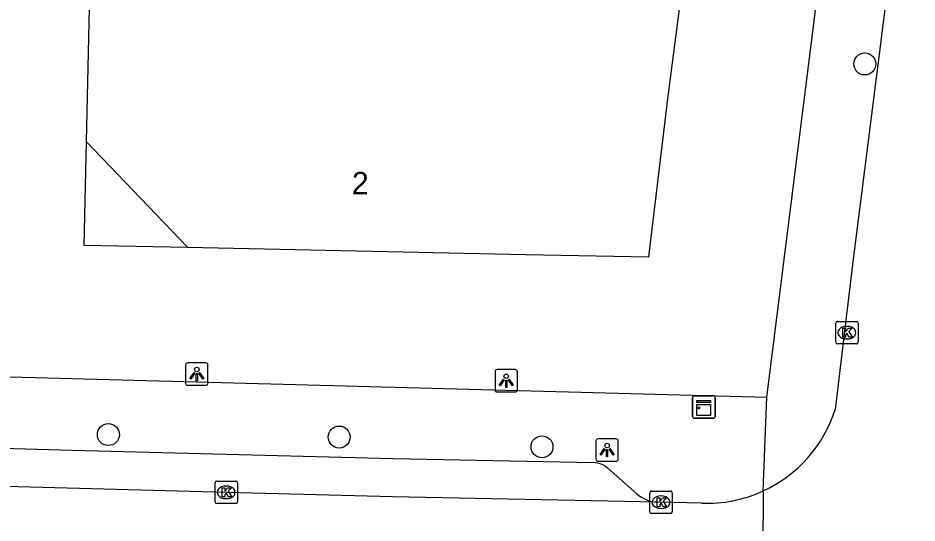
# Model space of a CAD drawing. Extents: x 160026 to 161302, y 384757 to 385701.
# Drawn here: x 160681.36 to 160721.38, y 384901.34 to 384923.84 of the extents above; entities that cross this region are included whole.
import ezdxf

# ---------------------------------------------------------------- set-up
doc = ezdxf.new("R2010")
doc.units = 0
for name, color, linetype in [('IMGEO_Boom', 7, 'Continuous'), ('IMGEO_Kast', 7, 'Continuous'), ('IMGEO_Kolk', 7, 'Continuous'), ('IMGEO_Lichtpunt', 7, 'Continuous'), ('IMGEO_Pand', 7, 'Continuous'), ('IMGEO_Pand_nummerreeks', 7, 'Continuous'), ('IMGEO_Pand_overbouw', 7, 'Continuous'), ('IMGEO_Rijbaan_lokaal_open', 7, 'Continuous'), ('IMGEO_Voetpad_open', 7, 'Continuous')]:
    doc.layers.add(name, color=color, linetype=linetype)

msp = doc.modelspace()

# ---------------------------------------------------------------- linework, layer by layer
at = {"layer": 'IMGEO_Boom'}
for centre in [(160719.052, 384921.79), (160685.378, 384905.282), (160695.653, 384905.17), (160704.683, 384904.737)]:
    msp.add_circle(centre, 0.489, dxfattribs=at)
at = {"layer": 'IMGEO_Kast'}
for p, q in [((160711.385, 384906.084), (160711.385, 384906.925)), ((160711.385, 384906.925), (160711.385, 384906.084)), ((160711.46, 384907.009), (160712.301, 384907.009)), ((160712.301, 384907.009), (160711.46, 384907.009)), ((160712.385, 384906.934), (160712.385, 384906.093)), ((160712.385, 384906.093), (160712.385, 384906.934)), ((160712.31, 384906.009), (160711.469, 384906.009)), ((160711.469, 384906.009), (160712.31, 384906.009))]:
    msp.add_line(p, q, dxfattribs=at)
for points in [[(160711.58, 384906.799), (160712.18, 384906.799), (160712.18, 384906.714), (160711.58, 384906.714), (160711.58, 384906.799)], [(160711.58, 384906.624), (160712.18, 384906.624), (160712.18, 384906.135), (160711.58, 384906.135), (160711.58, 384906.624)]]:
    msp.add_lwpolyline(points, dxfattribs=at)
msp.add_circle((160711.664, 384906.473), 0.0377, dxfattribs=at)
for centre, start, end in [((160711.463, 384906.931), 92.4484, 184.2845), ((160711.463, 384906.931), 92.4484, 184.2845), ((160712.307, 384906.931), 2.4484, 94.2845), ((160712.307, 384906.931), 2.4484, 94.2845), ((160711.463, 384906.087), 182.4484, 274.2845), ((160711.463, 384906.087), 182.4484, 274.2845), ((160712.307, 384906.087), 272.4484, 4.2845), ((160712.307, 384906.087), 272.4484, 4.2845)]:
    msp.add_arc(centre, 0.0779, start, end, dxfattribs=at)
at = {"layer": 'IMGEO_Kolk'}
for p, q in [((160717.756, 384909.394), (160717.756, 384910.246)), ((160717.831, 384910.32), (160718.683, 384910.32)), ((160718.244, 384910.1), (160718.269, 384910.1)), ((160718.757, 384910.246), (160718.757, 384909.394)), ((160718.267, 384909.54), (160718.242, 384909.54)), ((160718.683, 384909.32), (160717.831, 384909.32)), ((160690.126, 384902.282), (160690.126, 384903.134)), ((160690.201, 384903.208), (160691.053, 384903.208)), ((160691.127, 384903.134), (160691.127, 384902.282)), ((160690.614, 384902.988), (160690.639, 384902.988)), ((160709.556, 384902.768), (160710.408, 384902.768)), ((160690.637, 384902.428), (160690.612, 384902.428)), ((160709.481, 384901.842), (160709.481, 384902.694)), ((160709.969, 384902.548), (160709.994, 384902.548)), ((160710.482, 384902.694), (160710.482, 384901.842)), ((160691.053, 384902.208), (160690.201, 384902.208)), ((160709.992, 384901.988), (160709.967, 384901.988)), ((160710.408, 384901.768), (160709.556, 384901.768))]:
    msp.add_line(p, q, dxfattribs=at)
for points in [[(160717.756, 384909.394), (160717.756, 384910.246)], [(160717.831, 384910.32), (160718.683, 384910.32)], [(160718.077, 384910.02), (160718.2, 384910.02), (160718.2, 384909.869), (160718.33, 384910.02), (160718.494, 384910.02), (160718.348, 384909.869), (160718.501, 384909.62), (160718.349, 384909.62), (160718.264, 384909.784), (160718.2, 384909.717), (160718.2, 384909.62), (160718.077, 384909.62), (160718.077, 384910.02)], [(160718.757, 384910.246), (160718.757, 384909.394)], [(160718.683, 384909.32), (160717.831, 384909.32)], [(160690.126, 384902.282), (160690.126, 384903.134)], [(160690.201, 384903.208), (160691.053, 384903.208)], [(160691.127, 384903.134), (160691.127, 384902.282)], [(160690.447, 384902.908), (160690.57, 384902.908), (160690.57, 384902.757), (160690.7, 384902.908), (160690.864, 384902.908), (160690.718, 384902.757), (160690.871, 384902.508), (160690.719, 384902.508), (160690.634, 384902.672), (160690.57, 384902.605), (160690.57, 384902.508), (160690.447, 384902.508), (160690.447, 384902.908)], [(160709.556, 384902.768), (160710.408, 384902.768)], [(160709.481, 384901.842), (160709.481, 384902.694)], [(160709.802, 384902.468), (160709.925, 384902.468), (160709.925, 384902.317), (160710.055, 384902.468), (160710.219, 384902.468), (160710.073, 384902.317), (160710.226, 384902.068), (160710.074, 384902.068), (160709.989, 384902.232), (160709.925, 384902.165), (160709.925, 384902.068), (160709.802, 384902.068), (160709.802, 384902.468)], [(160710.482, 384902.694), (160710.482, 384901.842)], [(160691.053, 384902.208), (160690.201, 384902.208)], [(160710.408, 384901.768), (160709.556, 384901.768)]]:
    msp.add_lwpolyline(points, dxfattribs=at)
for centre, start, end in [((160717.833, 384910.244), 91.552, 178.448), ((160717.833, 384910.244), 91.552, 178.448), ((160718.681, 384910.244), 1.552, 88.448), ((160718.681, 384910.244), 1.552, 88.448), ((160717.833, 384909.396), 181.552, 268.448), ((160717.833, 384909.396), 181.552, 268.448), ((160718.681, 384909.396), 271.552, 358.448), ((160718.681, 384909.396), 271.552, 358.448), ((160690.203, 384903.132), 91.552, 178.448), ((160690.203, 384903.132), 91.552, 178.448), ((160691.051, 384903.132), 1.552, 88.448), ((160691.051, 384903.132), 1.552, 88.448), ((160709.558, 384902.692), 91.552, 178.448), ((160709.558, 384902.692), 91.552, 178.448), ((160710.406, 384902.692), 1.552, 88.448), ((160710.406, 384902.692), 1.552, 88.448), ((160690.203, 384902.284), 181.552, 268.448), ((160690.203, 384902.284), 181.552, 268.448), ((160691.051, 384902.284), 271.552, 358.448), ((160691.051, 384902.284), 271.552, 358.448), ((160709.558, 384901.844), 181.552, 268.448), ((160709.558, 384901.844), 181.552, 268.448), ((160710.406, 384901.844), 271.552, 358.448), ((160710.406, 384901.844), 271.552, 358.448)]:
    msp.add_arc(centre, 0.0765, start, end, dxfattribs=at)
for centre, major_axis, ratio, start_param, end_param in [((160718.243, 384909.82), (-0.387, 0.002), 0.722429, 4.712389, 7.853982), ((160718.268, 384909.82), (-0.39, 0.002), 0.717154, 1.570796, 4.712389), ((160690.613, 384902.708), (-0.387, 0.002), 0.722429, 4.712389, 7.853982), ((160690.638, 384902.708), (-0.39, 0.002), 0.717154, 1.570796, 4.712389), ((160709.968, 384902.268), (-0.387, 0.002), 0.722429, 4.712389, 7.853982), ((160709.993, 384902.268), (-0.39, 0.002), 0.717154, 1.570796, 4.712389)]:
    msp.add_ellipse(centre, major_axis=major_axis, ratio=ratio, start_param=start_param, end_param=end_param, dxfattribs=at)
at = {"layer": 'IMGEO_Lichtpunt'}
for p, q in [((160688.818, 384908.382), (160688.818, 384907.575)), ((160688.818, 384908.382), (160688.818, 384907.575)), ((160689.72, 384908.477), (160688.912, 384908.477)), ((160689.72, 384908.477), (160688.912, 384908.477)), ((160689.814, 384907.575), (160689.814, 384908.382)), ((160689.814, 384907.575), (160689.814, 384908.382)), ((160702.591, 384908.081), (160702.591, 384907.274)), ((160702.591, 384908.081), (160702.591, 384907.274)), ((160703.493, 384908.176), (160702.685, 384908.176)), ((160703.493, 384908.176), (160702.685, 384908.176)), ((160703.587, 384907.274), (160703.587, 384908.081)), ((160703.587, 384907.274), (160703.587, 384908.081)), ((160688.912, 384907.481), (160689.72, 384907.481)), ((160688.912, 384907.481), (160689.72, 384907.481)), ((160702.685, 384907.18), (160703.493, 384907.18)), ((160702.685, 384907.18), (160703.493, 384907.18)), ((160707.082, 384904.995), (160707.082, 384904.188)), ((160707.082, 384904.995), (160707.082, 384904.188)), ((160707.984, 384905.09), (160707.176, 384905.09)), ((160707.984, 384905.09), (160707.176, 384905.09)), ((160708.078, 384904.188), (160708.078, 384904.995)), ((160708.078, 384904.188), (160708.078, 384904.995)), ((160707.176, 384904.094), (160707.984, 384904.094)), ((160707.176, 384904.094), (160707.984, 384904.094))]:
    msp.add_line(p, q, dxfattribs=at)
for points in [[(160689.192, 384908.046), (160689.231, 384908.018), (160689.043, 384907.756), (160689.005, 384907.783), (160689.192, 384908.046)], [(160689.294, 384907.998), (160689.341, 384907.998), (160689.341, 384907.676), (160689.294, 384907.676), (160689.294, 384907.998)], [(160689.404, 384908.018), (160689.442, 384908.045), (160689.629, 384907.783), (160689.59, 384907.755), (160689.404, 384908.018)], [(160702.965, 384907.745), (160703.004, 384907.717), (160702.816, 384907.455), (160702.778, 384907.482), (160702.965, 384907.745)], [(160703.067, 384907.697), (160703.114, 384907.697), (160703.114, 384907.375), (160703.067, 384907.375), (160703.067, 384907.697)], [(160703.177, 384907.717), (160703.215, 384907.744), (160703.402, 384907.482), (160703.363, 384907.454), (160703.177, 384907.717)], [(160707.456, 384904.659), (160707.495, 384904.631), (160707.307, 384904.369), (160707.269, 384904.396), (160707.456, 384904.659)], [(160707.558, 384904.611), (160707.605, 384904.611), (160707.605, 384904.289), (160707.558, 384904.289), (160707.558, 384904.611)], [(160707.668, 384904.631), (160707.706, 384904.658), (160707.893, 384904.396), (160707.854, 384904.368), (160707.668, 384904.631)]]:
    msp.add_lwpolyline(points, dxfattribs=at)
for centre in [(160689.317, 384908.18), (160703.09, 384907.879), (160707.581, 384904.793)]:
    msp.add_circle(centre, 0.0994, dxfattribs=at)
for centre, start, end in [((160688.912, 384908.382), 90, 180), ((160688.912, 384908.382), 90, 180), ((160689.72, 384908.382), 0, 90), ((160689.72, 384908.382), 0, 90), ((160702.685, 384908.081), 90, 180), ((160702.685, 384908.081), 90, 180), ((160703.493, 384908.081), 0, 90), ((160703.493, 384908.081), 0, 90), ((160688.912, 384907.575), 180, 270), ((160688.912, 384907.575), 180, 270), ((160689.72, 384907.575), 270, 0), ((160689.72, 384907.575), 270, 360), ((160702.685, 384907.274), 180, 270), ((160702.685, 384907.274), 180, 270), ((160703.493, 384907.274), 270, 0), ((160703.493, 384907.274), 270, 360), ((160707.176, 384904.995), 90, 180), ((160707.176, 384904.995), 90, 180), ((160707.984, 384904.995), 0, 90), ((160707.984, 384904.995), 0, 90), ((160707.176, 384904.188), 180, 270), ((160707.176, 384904.188), 180, 270), ((160707.984, 384904.188), 270, 0), ((160707.984, 384904.188), 270, 360)]:
    msp.add_arc(centre, 0.0946, start, end, dxfattribs=at)
at = {"layer": 'IMGEO_Pand'}
msp.add_lwpolyline([(160711.433, 384929.193), (160712.122, 384934.562), (160713.114, 384942.294), (160707.72, 384942.986), (160691.177, 384945.074), (160684.886, 384940.208), (160684.396, 384918.328), (160688.9, 384913.622), (160703.967, 384913.306), (160709.434, 384913.191), (160710.299, 384920.351), (160710.976, 384925.626), (160710.987, 384925.717), (160711.425, 384929.13), (160711.433, 384929.193)], dxfattribs=at)
at = {"layer": 'IMGEO_Pand_overbouw'}
msp.add_lwpolyline([(160688.9, 384913.622), (160684.396, 384918.328), (160684.293, 384913.719)], close=True, dxfattribs=at)
at = {"layer": 'IMGEO_Rijbaan_lokaal_open'}
for points in [[(160722.005, 384940.911), (160721.629, 384937.93), (160719.946, 384924.212), (160718.522, 384912.973), (160717.734, 384906.397)], [(160709.828, 384902.269), (160698.023, 384902.51), (160690.1, 384902.721), (160674.224, 384903.144), (160663.708, 384903.619)], [(160714.535, 384902.774), (160714.497, 384897.457)], [(160711.776, 384902.229), (160709.828, 384902.269)]]:
    msp.add_lwpolyline(points, dxfattribs=at)
for centre, radius, start, end in [((160712.032, 384908.208), 5.982, 294.7312, 342.3817), ((160712.029, 384908.203), 5.98, 267.5736, 294.7745)]:
    msp.add_arc(centre, radius, start, end, dxfattribs=at)
at = {"layer": 'IMGEO_Voetpad_open'}
for points in [[(160714.697, 384906.942), (160720.402, 384952.382)], [(160672.719, 384908.083), (160714.697, 384906.942)], [(160714.535, 384902.774), (160714.697, 384906.942)], [(160666.431, 384905.18), (160669.456, 384905.106), (160674.272, 384904.847), (160678.054, 384904.746), (160683.761, 384904.594), (160698.063, 384904.213), (160706.972, 384904.031)], [(160707.614, 384903.781), (160708.9, 384902.644)]]:
    msp.add_lwpolyline(points, dxfattribs=at)
for centre, radius, start, end in [((160706.952, 384903.03), 1.002, 48.6085, 88.8388), ((160709.881, 384903.736), 1.468, 228.0667, 267.9265)]:
    msp.add_arc(centre, radius, start, end, dxfattribs=at)

# ---------------------------------------------------------------- texts
at = {"layer": 'IMGEO_Pand_nummerreeks'}
msp.add_text('2', height=1, rotation=358.7968, dxfattribs=at).set_placement((160696.209, 384915.988))

doc.saveas('drawing.dxf')
